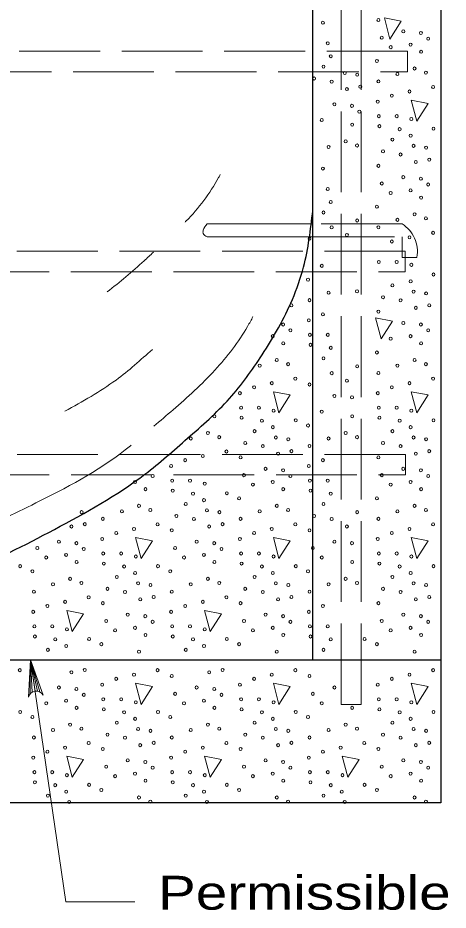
# Model space of a CAD drawing. Extents: x 1329.9 to 1363.9, y 715.5 to 737.5.
# Drawn here: x 1344.184 to 1346.165, y 717.971 to 722.082 of the extents above; entities that cross this region are included whole.
import ezdxf

# ---------------------------------------------------------------- set-up
doc = ezdxf.new("R2010")
doc.units = 0
doc.header["$LTSCALE"] = 0.062
doc.linetypes.add('LONG_DASHED', pattern=[7.5, 6, -1.5])
doc.layers.add('1', color=7, linetype='Continuous', lineweight=13)

msp = doc.modelspace()

# ---------------------------------------------------------------- linework, layer by layer
at = {"layer": '1', "linetype": 'LONG_DASHED'}
for p, q in [((1345.76417, 718.91875), (1345.76417, 728.66458)), ((1345.67267, 718.91875), (1345.67267, 728.64083)), ((1345.95292, 721.132), (1345.54142, 721.132)), ((1345.67267, 718.91875), (1345.76417, 718.91875))]:
    msp.add_line(p, q, dxfattribs=at)
at = {"layer": '1', "lineweight": 25}
for p, q in [((1345.54217, 721.19308), (1345.54217, 728.652)), ((1345.54217, 719.1235), (1345.54217, 721.19308))]:
    msp.add_line(p, q, dxfattribs=at)
at = {"layer": '1'}
for p, q in [((1345.54142, 721.132), (1345.05542, 721.132)), ((1345.05542, 721.07342), (1345.54625, 721.07342)), ((1344.24133, 718.96758), (1344.242, 719.1235)), ((1344.26342, 718.9795), (1344.242, 719.1235)), ((1344.25025, 718.97483), (1344.242, 719.1235)), ((1344.27425, 718.9795), (1344.242, 719.1235)), ((1344.28542, 718.976), (1344.242, 719.1235))]:
    msp.add_line(p, q, dxfattribs=at)
at = {"layer": '1', "lineweight": 25}
for points in [[(1346.13117, 728.65933), (1346.13117, 718.46475), (1340.5145, 718.46475), (1340.5145, 718.71467)], [(1340.02358, 719.1235), (1340.5145, 719.1235), (1346.13117, 719.1235)]]:
    msp.add_lwpolyline(points, dxfattribs=at)
at = {"layer": '1'}
for points in [[(1345.87175, 722.08125), (1345.89742, 721.98392), (1345.94967, 722.06608)], [(1345.99517, 721.70258), (1346.02083, 721.60533), (1346.073, 721.6875)], [(1345.83067, 720.70008), (1345.85633, 720.60283), (1345.90858, 720.685)], [(1345.36075, 720.35933), (1345.38642, 720.262), (1345.43858, 720.34417)], [(1345.99517, 720.35933), (1346.02083, 720.262), (1346.073, 720.34417)], [(1344.72633, 719.68767), (1344.752, 719.59042), (1344.80425, 719.67258)], [(1345.36075, 719.68767), (1345.38642, 719.59042), (1345.43858, 719.67258)], [(1345.99517, 719.68767), (1346.02083, 719.59042), (1346.073, 719.67258)], [(1344.40917, 719.35192), (1344.43483, 719.2545), (1344.487, 719.33667)], [(1345.04358, 719.35192), (1345.06917, 719.2545), (1345.12142, 719.33667)], [(1344.72633, 719.01608), (1344.752, 718.91867), (1344.80425, 719.00083)], [(1345.36075, 719.01608), (1345.38642, 718.91867), (1345.43858, 719.00083)], [(1345.99517, 719.01608), (1346.02083, 718.91867), (1346.073, 719.00083)], [(1344.40917, 718.68017), (1344.43483, 718.58292), (1344.487, 718.66508)], [(1345.04358, 718.68017), (1345.06917, 718.58292), (1345.12142, 718.66508)], [(1345.67792, 718.68017), (1345.70358, 718.58292), (1345.75583, 718.66508)]]:
    msp.add_lwpolyline(points, close=True, dxfattribs=at)
at = {"layer": '1', "linetype": 'LONG_DASHED'}
for points in [[(1345.97833, 721.92783), (1340.6625, 721.92783), (1340.6625, 721.83283), (1345.97833, 721.83283)], [(1345.96808, 721.00608), (1340.65225, 721.00608), (1340.65225, 720.91108), (1345.96808, 720.91108)], [(1345.96875, 720.07075), (1340.65292, 720.07075), (1340.65292, 719.97583), (1345.96875, 719.97583)]]:
    msp.add_lwpolyline(points, close=True, dxfattribs=at)
msp.add_lwpolyline([(1345.54625, 721.07342), (1345.95292, 721.07342), (1345.95292, 720.97775), (1346.02125, 720.97775)], dxfattribs=at)
at = {"layer": '1'}
for points in [[(1344.23342, 718.95217), (1344.242, 719.1235), (1344.3, 718.962)], [(1344.242, 719.1235), (1344.40517, 718.00908), (1344.72242, 718.00908)]]:
    msp.add_lwpolyline(points, dxfattribs=at)
msp.add_arc((1344.26874, 718.94365), 0.03631, 30.52372, 166.34985, dxfattribs=at)
for centre in [(1345.84415, 722.07165), (1345.58886, 722.05894), (1345.85959, 721.99004), (1345.95892, 722.01909), (1346.03975, 722.01209), (1345.61122, 721.96463), (1345.99233, 721.95831), (1346.07343, 721.98551), (1345.90072, 721.9465), (1346.0406, 721.92534), (1345.62491, 721.9048), (1345.83728, 721.88303), (1345.59145, 721.85672), (1345.68914, 721.82773), (1346.01063, 721.84827), (1346.06286, 721.82924), (1345.54836, 721.80204), (1345.62914, 721.78782), (1345.7465, 721.8195), (1345.84415, 721.78866), (1345.9318, 721.82291), (1345.69935, 721.75334), (1345.76104, 721.76426), (1346.09622, 721.76303), (1345.90605, 721.72312), (1345.98747, 721.74215), (1345.64172, 721.68327), (1345.72256, 721.67627), (1345.84103, 721.69592), (1345.75623, 721.64968), (1345.84616, 721.62881), (1345.92842, 721.62881), (1345.58352, 721.61067), (1345.7234, 721.58952), (1345.84869, 721.58258), (1345.99603, 721.61521), (1345.94211, 721.56898), (1345.9926, 721.53903), (1346.09796, 721.57077), (1345.69343, 721.51245), (1345.90865, 721.5209), (1345.6146, 721.48709), (1345.74566, 721.49342), (1345.86556, 721.46621), (1346.00634, 721.4919), (1346.0637, 721.48368), (1345.94634, 721.452), (1346.01655, 721.41752), (1346.07824, 721.42843), (1345.58886, 721.3873), (1345.84415, 721.4), (1345.95892, 721.34744), (1346.03975, 721.34045), (1345.61122, 721.29299), (1345.85959, 721.3184), (1346.07343, 721.31386), (1345.90072, 721.27485), (1345.99233, 721.28666), (1346.0406, 721.25369), (1345.62491, 721.23315), (1345.83728, 721.21138), (1345.59145, 721.18507), (1346.01063, 721.17662), (1345.7465, 721.14785), (1345.9318, 721.15127), (1346.06286, 721.15759), (1345.62914, 721.11617), (1345.84415, 721.11701), (1346.09622, 721.09138), (1345.52695, 721.06418), (1345.69935, 721.0817), (1345.90605, 721.05147), (1345.98747, 721.0705), (1345.58352, 720.93903), (1345.84616, 720.95716), (1345.92842, 720.95716), (1345.99603, 720.94356), (1346.09796, 720.89912), (1345.52008, 720.87556), (1345.90865, 720.84925), (1345.9926, 720.86739), (1345.6146, 720.81545), (1345.74566, 720.82177), (1346.00634, 720.82026), (1346.0637, 720.81203), (1345.44384, 720.75679), (1345.52695, 720.78119), (1345.86556, 720.79457), (1345.94634, 720.78035), (1346.07824, 720.75679), (1345.58886, 720.71565), (1345.84415, 720.72835), (1346.01655, 720.74587), (1345.52383, 720.68845), (1345.95892, 720.6758), (1345.40536, 720.6688), (1345.43903, 720.64222), (1346.03975, 720.6688), (1346.07343, 720.64222), (1345.35793, 720.61501), (1345.52896, 720.62134), (1345.61122, 720.62134), (1345.90072, 720.60321), (1345.99233, 720.61501), (1345.4062, 720.58205), (1345.5315, 720.57511), (1345.62491, 720.56151), (1346.0406, 720.58205), (1345.59145, 720.51343), (1345.83728, 720.53973), (1345.2974, 720.47962), (1345.37623, 720.50498), (1345.42846, 720.48595), (1345.7465, 720.47621), (1345.9318, 720.47962), (1346.01063, 720.50498), (1346.06286, 720.48595), (1345.62914, 720.44453), (1345.84415, 720.44537), (1345.35307, 720.39886), (1345.46182, 720.41973), (1345.52695, 720.39253), (1345.69935, 720.41005), (1345.98747, 720.39886), (1346.09622, 720.41973), (1345.20663, 720.35263), (1345.27166, 720.37983), (1345.84103, 720.35263), (1345.90605, 720.37983), (1345.64172, 720.33998), (1345.72256, 720.33298), (1345.21176, 720.28552), (1345.29402, 720.28552), (1345.36164, 720.27192), (1345.58352, 720.26738), (1345.84616, 720.28552), (1345.92842, 720.28552), (1345.99603, 720.27192), (1345.089, 720.24623), (1345.2143, 720.23929), (1345.30771, 720.22568), (1345.46356, 720.22748), (1345.7234, 720.24623), (1345.84869, 720.23929), (1345.94211, 720.22568), (1346.09796, 720.22748), (1345.3582, 720.19574), (1345.52008, 720.20391), (1345.9926, 720.19574), (1344.9802, 720.1438), (1345.05903, 720.16915), (1345.11126, 720.15012), (1345.27425, 720.17761), (1345.37194, 720.14861), (1345.4293, 720.14039), (1345.6146, 720.1438), (1345.69343, 720.16915), (1345.74566, 720.15012), (1345.90865, 720.17761), (1346.00634, 720.14861), (1346.0637, 720.14039), (1345.23116, 720.12292), (1345.31194, 720.10871), (1345.52695, 720.10955), (1345.86556, 720.12292), (1345.94634, 720.10871), (1345.03587, 720.06303), (1345.14462, 720.08391), (1345.38215, 720.07423), (1345.44384, 720.08514), (1346.01655, 720.07423), (1346.07824, 720.08514), (1344.88943, 720.0168), (1344.95446, 720.044), (1345.20975, 720.05671), (1345.52383, 720.0168), (1345.58886, 720.044), (1345.84415, 720.05671), (1345.22519, 719.9751), (1345.32452, 720.00415), (1345.40536, 719.99716), (1345.85959, 719.9751), (1345.95892, 720.00415), (1346.03975, 719.99716), (1344.72354, 719.94337), (1344.80463, 719.97057), (1344.89456, 719.94969), (1344.97682, 719.94969), (1345.04444, 719.93609), (1345.35793, 719.94337), (1345.43903, 719.97057), (1345.52896, 719.94969), (1345.61122, 719.94969), (1345.99233, 719.94337), (1346.07343, 719.97057), (1344.7718, 719.9104), (1344.8971, 719.90346), (1345.26632, 719.93156), (1345.4062, 719.9104), (1345.5315, 719.90346), (1345.90072, 719.93156), (1346.0406, 719.9104), (1344.99051, 719.88986), (1345.041, 719.85992), (1345.14636, 719.89165), (1345.20288, 719.86809), (1345.62491, 719.88986), (1345.83728, 719.86809), (1344.74183, 719.83333), (1344.79406, 719.8143), (1344.95705, 719.84178), (1345.05474, 719.81279), (1345.37623, 719.83333), (1345.42846, 719.8143), (1345.59145, 719.84178), (1346.01063, 719.83333), (1346.06286, 719.8143), (1344.47771, 719.80456), (1344.57535, 719.77372), (1344.663, 719.80798), (1344.91396, 719.7871), (1344.99474, 719.77288), (1345.1121, 719.80456), (1345.20975, 719.77372), (1345.2974, 719.80798), (1345.54836, 719.7871), (1345.62914, 719.77288), (1345.7465, 719.80456), (1345.84415, 719.77372), (1345.9318, 719.80798), (1344.43055, 719.73841), (1344.49224, 719.74932), (1344.82742, 719.74809), (1345.06495, 719.73841), (1345.12664, 719.74932), (1345.46182, 719.74809), (1345.69935, 719.73841), (1346.09622, 719.74809), (1344.63726, 719.70818), (1344.71867, 719.72721), (1344.89255, 719.72089), (1345.27166, 719.70818), (1345.35307, 719.72721), (1345.52695, 719.72089), (1345.90605, 719.70818), (1345.98747, 719.72721), (1344.37292, 719.66833), (1344.45376, 719.66133), (1344.57223, 719.68098), (1345.00732, 719.66833), (1345.08816, 719.66133), (1345.20663, 719.68098), (1345.64172, 719.66833), (1345.72256, 719.66133), (1345.84103, 719.68098), (1344.27359, 719.63928), (1344.40634, 719.60755), (1344.48743, 719.63475), (1344.57736, 719.61387), (1344.65962, 719.61387), (1344.90799, 719.63928), (1345.04074, 719.60755), (1345.12183, 719.63475), (1345.21176, 719.61387), (1345.29402, 719.61387), (1345.54239, 719.63928), (1345.84616, 719.61387), (1345.92842, 719.61387), (1344.31472, 719.59574), (1344.4546, 719.57458), (1344.5799, 719.56764), (1344.72724, 719.60027), (1344.94912, 719.59574), (1345.089, 719.57458), (1345.2143, 719.56764), (1345.36164, 719.60027), (1345.58352, 719.59574), (1345.7234, 719.57458), (1345.84869, 719.56764), (1345.99603, 719.60027), (1344.19476, 719.55583), (1344.25128, 719.53227), (1344.67331, 719.55404), (1344.7238, 719.52409), (1344.82916, 719.55583), (1344.88568, 719.53227), (1345.30771, 719.55404), (1345.3582, 719.52409), (1345.46356, 719.55583), (1345.52008, 719.53227), (1345.94211, 719.55404), (1345.9926, 719.52409), (1346.09796, 719.55583), (1344.42463, 719.49751), (1344.63985, 719.50596), (1345.05903, 719.49751), (1345.27425, 719.50596), (1345.69343, 719.49751), (1345.90865, 719.50596), (1344.3458, 719.47215), (1344.47686, 719.47848), (1344.59676, 719.45128), (1344.73755, 719.47697), (1344.79491, 719.46874), (1344.9802, 719.47215), (1345.11126, 719.47848), (1345.23116, 719.45128), (1345.37194, 719.47697), (1345.4293, 719.46874), (1345.6146, 719.47215), (1345.74566, 719.47848), (1345.86556, 719.45128), (1346.00634, 719.47697), (1346.0637, 719.46874), (1344.25815, 719.4379), (1344.51022, 719.41227), (1344.67754, 719.43706), (1344.74775, 719.40258), (1344.80944, 719.4135), (1344.89255, 719.4379), (1345.14462, 719.41227), (1345.31194, 719.43706), (1345.38215, 719.40258), (1345.44384, 719.4135), (1345.52695, 719.4379), (1345.94634, 719.43706), (1346.01655, 719.40258), (1346.07824, 719.4135), (1344.32006, 719.37236), (1344.40147, 719.39139), (1344.57535, 719.38506), (1344.95446, 719.37236), (1345.03587, 719.39139), (1345.20975, 719.38506), (1345.58886, 719.37236), (1345.84415, 719.38506), (1344.25503, 719.34516), (1344.69012, 719.33251), (1344.77096, 719.32551), (1344.88943, 719.34516), (1345.32452, 719.33251), (1345.40536, 719.32551), (1345.52383, 719.34516), (1345.95892, 719.33251), (1346.03975, 719.32551), (1344.26016, 719.27805), (1344.34242, 719.27805), (1344.59079, 719.30346), (1344.80463, 719.29893), (1344.89456, 719.27805), (1344.97682, 719.27805), (1345.22519, 719.30346), (1345.43903, 719.29893), (1345.52896, 719.27805), (1345.61122, 719.27805), (1345.85959, 719.30346), (1346.07343, 719.29893), (1344.41004, 719.26445), (1344.63192, 719.25991), (1344.72354, 719.27172), (1344.7718, 719.23876), (1345.04444, 719.26445), (1345.26632, 719.25991), (1345.35793, 719.27172), (1345.4062, 719.23876), (1345.90072, 719.25991), (1345.99233, 719.27172), (1346.0406, 719.23876), (1344.2627, 719.23182), (1344.35611, 719.21822), (1344.51196, 719.22001), (1344.56848, 719.19644), (1344.8971, 719.23182), (1344.99051, 719.21822), (1345.14636, 719.22001), (1345.20288, 719.19644), (1345.5315, 719.23182), (1345.62491, 719.21822), (1345.78076, 719.22001), (1345.83728, 719.19644), (1344.32265, 719.17014), (1344.4066, 719.18827), (1344.74183, 719.16169), (1344.95705, 719.17014), (1345.041, 719.18827), (1345.37623, 719.16169), (1345.59145, 719.17014), (1346.01063, 719.16169), (1344.19302, 719.07644), (1344.49224, 719.07767), (1344.82742, 719.07644), (1345.12664, 719.07767), (1345.46182, 719.07644), (1346.09622, 719.07644), (1344.43055, 719.06676), (1344.63726, 719.03654), (1344.71867, 719.05557), (1344.89255, 719.04924), (1345.06495, 719.06676), (1345.27166, 719.03654), (1345.35307, 719.05557), (1345.52695, 719.04924), (1345.90605, 719.03654), (1345.98747, 719.05557), (1344.37292, 718.99668), (1344.45376, 718.98969), (1344.57223, 719.00933), (1345.00732, 718.99668), (1345.08816, 718.98969), (1345.20663, 719.00933), (1345.64172, 718.99668), (1345.84103, 719.00933), (1344.48743, 718.9631), (1344.90799, 718.96764), (1345.12183, 718.9631), (1345.54239, 718.96764), (1344.31472, 718.92409), (1344.40634, 718.9359), (1344.57736, 718.94223), (1344.65962, 718.94223), (1344.72724, 718.92862), (1344.94912, 718.92409), (1345.04074, 718.9359), (1345.21176, 718.94223), (1345.29402, 718.94223), (1345.36164, 718.92862), (1345.58352, 718.92409), (1345.84616, 718.94223), (1345.92842, 718.94223), (1345.99603, 718.92862), (1344.19476, 718.88418), (1344.4546, 718.90293), (1344.5799, 718.89599), (1344.67331, 718.88239), (1344.82916, 718.88418), (1345.089, 718.90293), (1345.2143, 718.89599), (1345.30771, 718.88239), (1345.46356, 718.88418), (1345.7234, 718.90293), (1345.84869, 718.89599), (1345.94211, 718.88239), (1346.09796, 718.88418), (1344.25128, 718.86062), (1344.42463, 718.82586), (1344.63985, 718.83431), (1344.7238, 718.85245), (1344.88568, 718.86062), (1345.05903, 718.82586), (1345.27425, 718.83431), (1345.3582, 718.85245), (1345.52008, 718.86062), (1345.69343, 718.82586), (1345.90865, 718.83431), (1345.9926, 718.85245), (1344.3458, 718.80051), (1344.47686, 718.80683), (1344.73755, 718.80532), (1344.79491, 718.79709), (1344.9802, 718.80051), (1345.11126, 718.80683), (1345.37194, 718.80532), (1345.4293, 718.79709), (1345.6146, 718.80051), (1345.74566, 718.80683), (1346.00634, 718.80532), (1346.0637, 718.79709), (1344.25815, 718.76625), (1344.59676, 718.77963), (1344.67754, 718.76541), (1344.80944, 718.74185), (1344.89255, 718.76625), (1345.23116, 718.77963), (1345.31194, 718.76541), (1345.44384, 718.74185), (1345.52695, 718.76625), (1345.86556, 718.77963), (1345.94634, 718.76541), (1346.07824, 718.74185), (1344.32006, 718.70071), (1344.40147, 718.71974), (1344.51022, 718.74062), (1344.57535, 718.71342), (1344.74775, 718.73094), (1344.95446, 718.70071), (1345.03587, 718.71974), (1345.14462, 718.74062), (1345.20975, 718.71342), (1345.38215, 718.73094), (1345.58886, 718.70071), (1345.67027, 718.71974), (1345.77902, 718.74062), (1345.84415, 718.71342), (1346.01655, 718.73094), (1344.25503, 718.67351), (1344.69012, 718.66086), (1344.88943, 718.67351), (1345.32452, 718.66086), (1345.52383, 718.67351), (1345.95892, 718.66086), (1344.59079, 718.63181), (1344.77096, 718.65387), (1344.80463, 718.62728), (1345.22519, 718.63181), (1345.40536, 718.65387), (1345.43903, 718.62728), (1345.85959, 718.63181), (1346.03975, 718.65387), (1346.07343, 718.62728), (1344.26016, 718.6064), (1344.34242, 718.6064), (1344.41004, 718.5928), (1344.63192, 718.58827), (1344.72354, 718.60008), (1344.89456, 718.6064), (1344.97682, 718.6064), (1345.04444, 718.5928), (1345.26632, 718.58827), (1345.35793, 718.60008), (1345.52896, 718.6064), (1345.61122, 718.6064), (1345.67883, 718.5928), (1345.90072, 718.58827), (1345.99233, 718.60008), (1344.2627, 718.56017), (1344.35611, 718.54657), (1344.51196, 718.54836), (1344.7718, 718.56711), (1344.8971, 718.56017), (1344.99051, 718.54657), (1345.14636, 718.54836), (1345.4062, 718.56711), (1345.5315, 718.56017), (1345.62491, 718.54657), (1345.78076, 718.54836), (1346.0406, 718.56711), (1344.32265, 718.49849), (1344.4066, 718.51663), (1344.56848, 718.5248), (1344.95705, 718.49849), (1345.041, 718.51663), (1345.20288, 718.5248), (1345.59145, 718.49849), (1345.6754, 718.51663), (1345.83728, 718.5248), (1344.42035, 718.4695), (1344.74183, 718.49004), (1344.79406, 718.47101), (1345.05474, 718.4695), (1345.37623, 718.49004), (1345.42846, 718.47101), (1345.68914, 718.4695), (1346.01063, 718.49004), (1346.06286, 718.47101)]:
    msp.add_ellipse(centre, major_axis=(0, 0.00718), ratio=0.944544, dxfattribs=at)
at = {"layer": '1', "linetype": 'LONG_DASHED'}
msp.add_ellipse((1345.88668, 721.005), major_axis=(0, -0.14504), ratio=0.944544, start_param=1.3817766, end_param=2.6372404, dxfattribs=at)
at = {"layer": '1'}
for points in [[(1344.95408, 721.14108), (1344.95808, 721.145), (1345.1085, 721.34608), (1345.11575, 721.35933)], [(1345.05542, 721.132), (1345.03758, 721.10292), (1345.03758, 721.0875), (1345.05542, 721.07342)], [(1344.59583, 720.819), (1344.76533, 720.96175), (1344.808, 721.00233)], [(1344.80967, 720.20075), (1344.89883, 720.27575), (1345.0915, 720.459), (1345.242, 720.66017), (1345.26675, 720.7055)], [(1344.40058, 720.2695), (1344.636, 720.41325), (1344.80358, 720.55442)], [(1343.97942, 719.70967), (1344.28592, 719.85617), (1344.70267, 720.11067), (1344.70558, 720.11308)]]:
    msp.add_spline(points, degree=3, dxfattribs=at)
at = {"layer": '1', "lineweight": 25}
msp.add_spline([(1341.53892, 719.12392), (1341.54858, 719.12442), (1342.16333, 719.16225), (1342.55242, 719.20425), (1342.97442, 719.27833), (1343.37542, 719.36125), (1343.934, 719.52492), (1344.35258, 719.725), (1344.76942, 719.9795), (1344.9655, 720.14458), (1345.15825, 720.32783), (1345.30867, 720.529), (1345.44808, 720.78467), (1345.49958, 720.93375), (1345.54217, 721.19308)], degree=3, dxfattribs=at)

# ---------------------------------------------------------------- texts
at = {"layer": '1', "width": 1.25}
msp.add_text('Permissible', height=0.156, dxfattribs=at).set_placement((1344.82933, 717.97317))

doc.saveas('drawing.dxf')
